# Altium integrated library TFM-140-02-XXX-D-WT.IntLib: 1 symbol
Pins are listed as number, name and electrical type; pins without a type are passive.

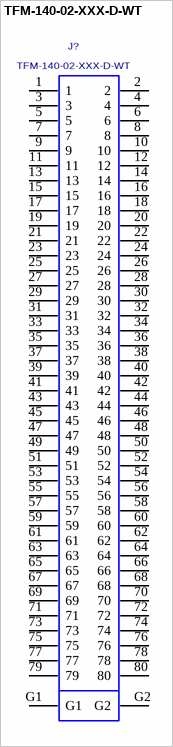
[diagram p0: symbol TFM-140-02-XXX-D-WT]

## TFM-140-02-XXX-D-WT
designator J?
0.050" TERMINAL STRIP, SURFACE MOUNT ASSEMBLY.; MANUFACTURER: SAMTEC
footprint TFM-140-02-XXX-D-WT
pins: 1, 2, 3, 4, 5, 6, 7, 8, 9, 10, 11, 12, 13, 14, 15, 16, 17, 18, 19, 20, 21, 22, 23, 24, 25, 26, 27, 28, 29, 30, 31, 32, 33, 34, 35, 36, 37, 38, 39, 40, 41, 42, 43, 44, 45, 46, 47, 48, 49, 50, 51, 52, 53, 54, 55, 56, 57, 58, 59, 60, 61, 62, 63, 64, 65, 66, 67, 68, 69, 70, 71, 72, 73, 74, 75, 76, 77, 78, 79, 80, G1, G2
